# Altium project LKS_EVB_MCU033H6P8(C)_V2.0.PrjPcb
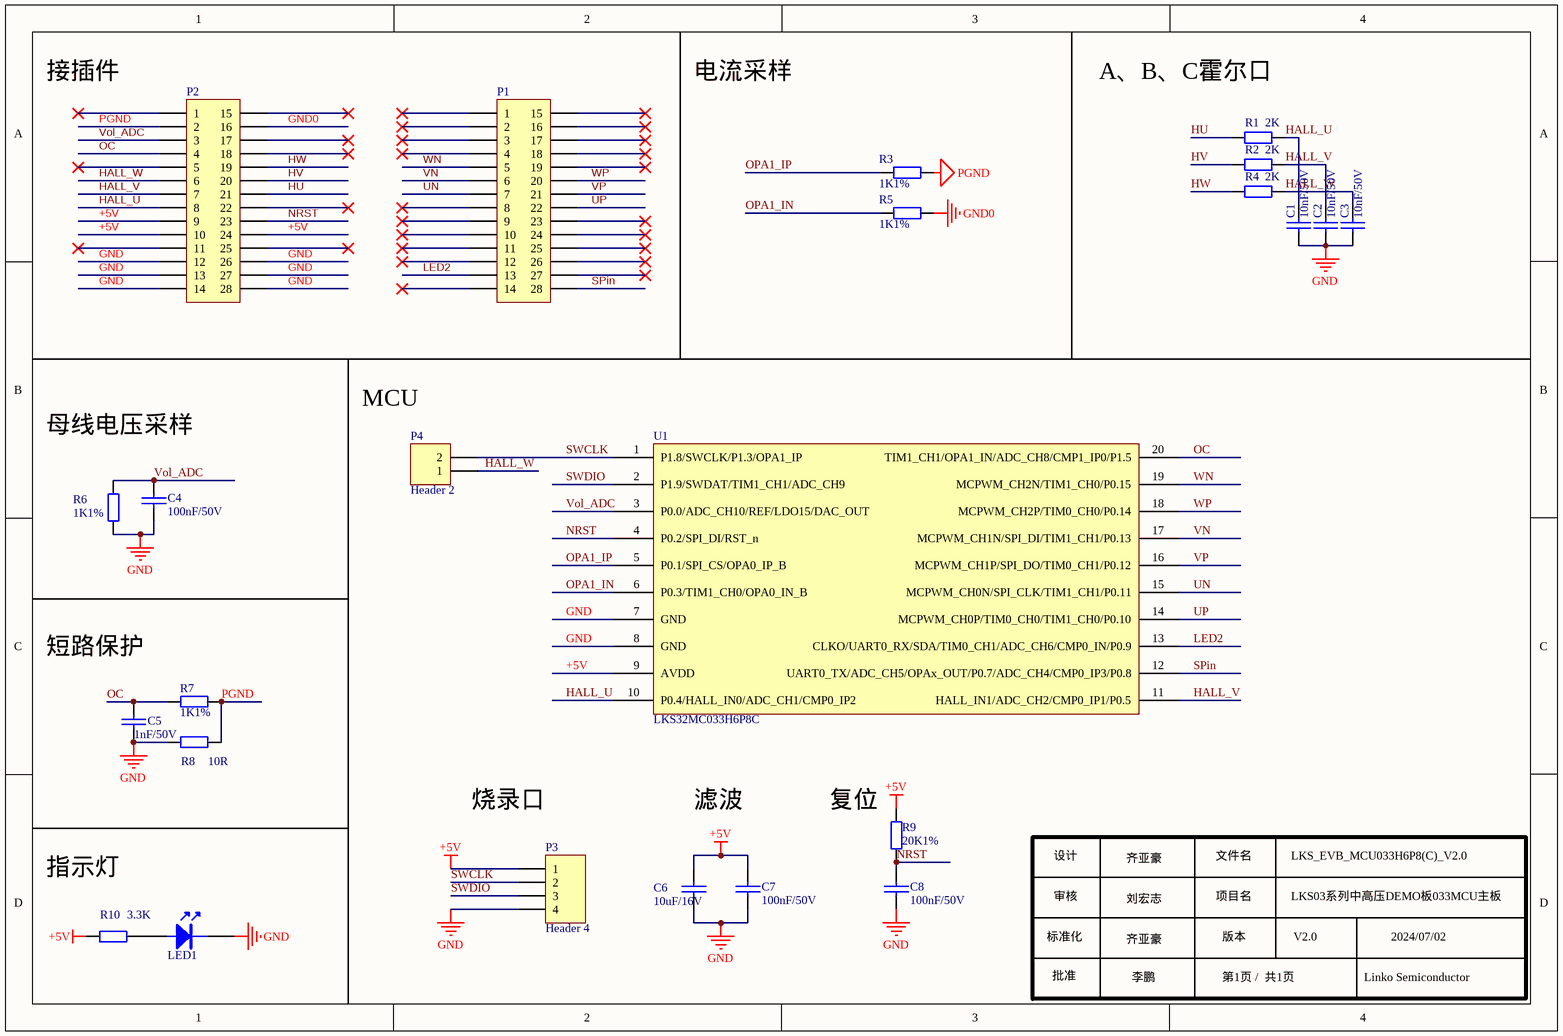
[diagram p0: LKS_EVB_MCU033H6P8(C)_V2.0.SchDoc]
1 sheet, 24 parts. Net scope: global (net labels, ports and power ports of the same name join across sheets).
Board file: LKS_EVB_MCU033H6P8(C)_V2.0.PcbDoc

## Sheet LKS_EVB_MCU033H6P8(C)_V2.0.SchDoc
size A4; SheetNumber: 1; SheetTotal: 1

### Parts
C1  10nF/50V  [0603C]
C2  10nF/50V  [0603C]
C3  10nF/50V  [0603C]
C4  100nF/50V  [0603C]
C5  1nF/50V  [0603C]
C6  10uF/16V  [0603C]
C7  100nF/50V  [0603C]
C8  100nF/50V  [0603C]
LED1  LED  [LED 0603R]  (value not drawn)
P1  Header 14X2A  [HDR 2X14 顶层]  (value not drawn)
P2  Header 14X2A  [HDR 2X14 顶层]  (value not drawn)
P3  Header 4  [HDR 1X4]
P4  Header 2  [HDR 1X2]
R1  2K  [0603R]
R2  2K  [0603R]
R3  1K1%  [0603R]
R4  2K  [0603R]
R5  1K1%  [0603R]
R6  1K1%  [0603R]
R7  1K1%  [0603R]
R8  10R  [0603R]
R9  20K1%  [0603R]
R10  3.3K  [0603R]
U1  LKS32MC033H6P8C  [TSSOP-20]

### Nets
+5V: C6.2 C7.2 P2.9 P2.10 P2.24 P3.1 R9.1 R10.1 U1.9(AVDD)
GND: C1.2 C2.2 C3.2 C4.1 C5.1 C6.1 C7.1 C8.2 LED1.2(K) P2.12 P2.13 P2.14 P2.26 P2.27 P2.28 P3.4 R6.1 R8.2 U1.7(GND) U1.8(GND)
GND0: P2.16 R5.1
PGND: P2.2 R3.1 R7.2 R8.1
HALL_U: C1.1 P2.8 R1.2 U1.10(P0.4/HALL_IN0/ADC_CH1/CMP0_IP2)
HALL_V: C2.1 P2.7 R2.2 U1.11(HALL_IN1/ADC_CH2/CMP0_IP1/P0.5)
HALL_W: C3.1 P2.6 P4.1 R4.2
HU: P2.21 R1.1
HV: P2.20 R2.1
HW: P2.19 R4.1
LED2: P1.13 U1.13(CLKO/UART0_RX/SDA/TIM0_CH1/ADC_CH6/CMP0_IN/P0.9)
NRST: C8.1 P2.23 R9.2 U1.4(P0.2/SPI_DI/RST_n)
OC: C5.2 P2.4 R7.1 U1.20(TIM1_CH1/OPA1_IN/ADC_CH8/CMP1_IP0/P1.5)
OPA1_IN: R5.2 U1.6(P0.3/TIM1_CH0/OPA0_IN_B)
OPA1_IP: R3.2 U1.5(P0.1/SPI_CS/OPA0_IP_B)
SPin: P1.28 U1.12(UART0_TX/ADC_CH5/OPAx_OUT/P0.7/ADC_CH4/CMP0_IP3/P0.8)
SWCLK: P3.2 P4.2 U1.1(P1.8/SWCLK/P1.3/OPA1_IP)
SWDIO: P3.3 U1.2(P1.9/SWDAT/TIM1_CH1/ADC_CH9)
UN: P1.7 U1.15(MCPWM_CH0N/SPI_CLK/TIM1_CH1/P0.11)
UP: P1.22 U1.14(MCPWM_CH0P/TIM0_CH0/TIM1_CH0/P0.10)
VN: P1.6 U1.17(MCPWM_CH1N/SPI_DI/TIM1_CH1/P0.13)
Vol_ADC: C4.2 P2.3 R6.2 U1.3(P0.0/ADC_CH10/REF/LDO15/DAC_OUT)
VP: P1.21 U1.16(MCPWM_CH1P/SPI_DO/TIM0_CH1/P0.12)
WN: P1.5 U1.19(MCPWM_CH2N/TIM1_CH0/P0.15)
WP: P1.20 U1.18(MCPWM_CH2P/TIM0_CH0/P0.14)
NetLED1_1: LED1.1(A) R10.2

Not connected (* = marked no-connect by the designer): P1 1* 2* 3* 4* 8* 9* 10* 11* 12* 14* 15* 16* 17* 18* 19* 23* 24* 25* 26* 27*; P2 1* 5* 11* 15* 17* 18* 22* 25*

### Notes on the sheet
- 接插件
- 电流采样
- A、B、C霍尔口
- 母线电压采样
- MCU
- 短路保护
- 烧录口
- 滤波
- (near R9) 复位
- 指示灯
- 设计
- 审核
- 齐亚豪
- 刘宏志
- 文件名
- 项目名
- LKS_EVB_MCU033H6P8(C)_V2.0
- LKS03系列中高压DEMO板033MCU主板
- 标准化
- 批准
- 李鹏
- 版本
- 第1页 /  共1页
- V2.0
- Linko Semiconductor
- 2024/07/02

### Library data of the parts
C1-C3 = CAP: Capacitor
C4-C8 = C: Capacitor
LED1 = LED: LED_Light
P1 P2 = Header 14X2A: Header, 14-Pin, Dual row
P3 = Header 4: Header, 4-Pin
P4 = Header 2: Header, 2-Pin
R1-R9 = Res: Resistor; Value: K
R10 = Res: Resistor; Value: 330
U1 = LKS32MC033H6P8C: 芯片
